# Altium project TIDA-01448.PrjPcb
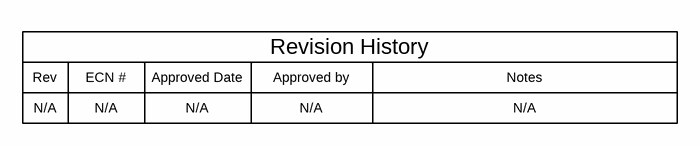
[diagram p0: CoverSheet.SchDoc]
CopyrightYear: 2015; EVM_Orderable: N/A; PCB_Layout: Who did the Layout?; PCB_Rev: E1; PRJ_Customer: Public Release; PRJ_Engineer: Enter name of project lead; PRJ_Number: TIDA-xxxxx; PRJ_Title: Change in menu Project|Project Options|Parameters; SCH_Rev: E1; TechSupport: http://www.ti.com/support; TID: ChangeMe!
3 sheets, 37 parts. Net scope: global (net labels, ports and power ports of the same name join across sheets).
Board file: TIDA-01448 Rev A1.PcbDoc
Sheets:
  CoverSheet.SchDoc
  TIDA-01448.SchDoc
  TID_Hardware.SchDoc

## Sheet CoverSheet.SchDoc
size 431 x 279 mm; Date: Not shown in title block; ApprovedBy: Not shown in title block; CheckedBy: Not shown in title block; Author: Not shown in title block; CompanyName: Not shown in title block; Engineer: Not shown in title block; Organization: Not shown in title block; Address1: Not shown in title block; Address2: Not shown in title block; Address3: Not shown in title block; Address4: Not shown in title block; DocumentNumber: 1; Revision: Use project parameter SCH_Rev; SheetNumber: 1; SheetTotal: 3; PageSetup: Record=PageOptions¦CenterHorizontal=True¦CenterVertical=True¦PrintScale=1.00¦XCorrection=1.00¦YCorrection=1.00¦PrintKind=0¦BorderSize=5000000¦LeftOffset=0¦BottomOffset=0¦Orientation=2¦PaperLength=1000¦PaperWidth=1000¦Scale=100¦PaperSource=15¦PrintQuality=600¦MediaType=1¦DitherType=10¦PaperKind=Letter¦PrintScaleMode=1

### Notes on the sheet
- Rev
- N/A
- ECN #
- Approved Date
- Approved by
- Revision History
- Notes

## Sheet TIDA-01448.SchDoc
size 431 x 279 mm; Date: Not shown in title block; ApprovedBy: Not shown in title block; CheckedBy: Not shown in title block; Author: Not shown in title block; CompanyName: Not shown in title block; Engineer: Not shown in title block; Organization: Not shown in title block; Address1: Not shown in title block; Address2: Not shown in title block; Address3: Not shown in title block; Address4: Not shown in title block; DocumentNumber: 1; Revision: Use project parameter SCH_Rev; SheetNumber: 2; SheetTotal: 3; PageSetup: Record=PageOptions¦CenterHorizontal=True¦CenterVertical=True¦PrintScale=1.00¦XCorrection=1.00¦YCorrection=1.00¦PrintKind=0¦BorderSize=5000000¦LeftOffset=0¦BottomOffset=0¦Orientation=2¦PaperLength=1000¦PaperWidth=1000¦Scale=100¦PaperSource=15¦PrintQuality=600¦MediaType=1¦DitherType=10¦PaperKind=Letter¦PrintScaleMode=1
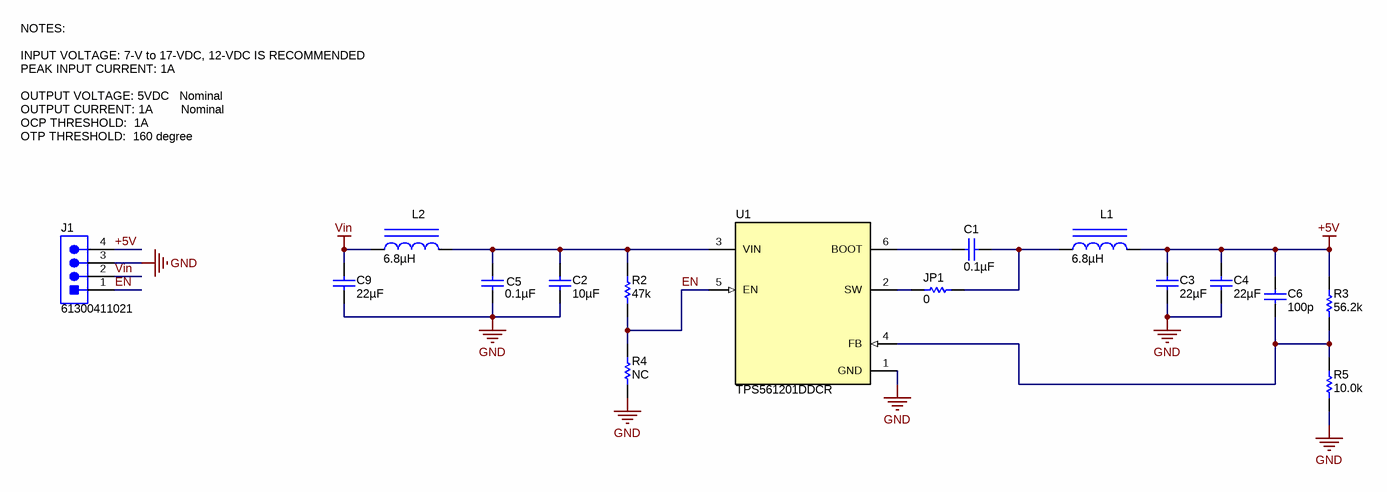
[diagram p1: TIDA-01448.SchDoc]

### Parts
C1  ValueDisplayed: 0.1µF  [0805_HV]  (hidden comment: GRM21BR71E104KA01L)
C2  ValueDisplayed: 10µF  [1206]  (hidden comment: GRM31CR71E106KA12L)
C3  ValueDisplayed: 22µF  [1206_190]  (hidden comment: GCM31CR71A226KE02)
C4  ValueDisplayed: 22µF  [1206_190]  (hidden comment: GCM31CR71A226KE02)
C5  ValueDisplayed: 0.1µF  [0603]  (hidden comment: GRM188R71E104KA01D)
C6  ValueDisplayed: 100p  [C/0805/SMT1]  (hidden comment: 06033C101KAT2A)
C9  ValueDisplayed: 22µF  [1206_190]  (hidden comment: C3216X5R1E226M160AB)
J1  61300411021  [Wurth_61300411021]
JP1  ValueDisplayed: 0  [JUMP-5]  (hidden comment: CRCW0603100KFKEA)
L1  ValueDisplayed: 6.8µH  [LPS8045B]  (hidden comment: ABG06A45M6R8)
L2  ValueDisplayed: 6.8µH  [LPS8045B]  (hidden comment: ABG03A15M6R8)
R2  ValueDisplayed: 47k  [0603]  (hidden comment: CRCW060347K0JNEA)
R3  ValueDisplayed: 56.2k  [0603]  (hidden comment: CRCW060356K2FKEA)
R4  ValueDisplayed: NC  [0603]  (hidden comment: CRCW0603150KFKEA)
R5  ValueDisplayed: 10.0k  [0603]  (hidden comment: CRCW060310K0FKEA)
U1  TPS561201DDCR  [DDC0006A_N]

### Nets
+5V: C3.1 C4.1 C6.1 J1.4 L1.2 R3.2
GND: C2.2 C3.2 C4.2 C5.2 C9.2 J1.3 R4.1 R5.1 U1.1(GND)
Vin: C9.1 J1.2 L2.1
EN: J1.1 R2.1 R4.2 U1.5(EN)
NetC1_1: C1.1 JP1.1 L1.1
NetC1_2: C1.2 U1.6(BOOT)
NetC2_1: C2.1 C5.1 L2.2 R2.2 U1.3(VIN)
NetC6_2: C6.2 R3.1 R5.2 U1.4(FB)
NetJP1_2: JP1.2 U1.2(SW)

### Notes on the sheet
- NOTES:
  INPUT VOLTAGE: 7-V to 17-VDC, 12-VDC IS RECOMMENDED
  PEAK INPUT CURRENT: 1A
  OUTPUT VOLTAGE: 5VDC   Nominal
  OUTPUT CURRENT: 1A        Nominal
  OCP THRESHOLD:  1A
  OTP THRESHOLD:  160 degree

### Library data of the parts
C1 = GRM21BR71E104KA01L: CAP, CERM, 0.1 µF, 25 V, +/- 10%, X7R, 0805; Manufacturer: MuRata; Polarized: N; CompType: Capacitor; Value: 0.1uF; U/M: EA; Cap_F: 0.0000001; Tolerance_%: 10; Value1: Unknown; VDC_V: 25; Value2: 25V; TaMin_C: -55; TaMax_C: 125; Cap_Case: 0805; AEC Category: Q200
C2 = GRM31CR71E106KA12L: CAP, CERM, 10 µF, 25 V, +/- 10%, X7R, 1206; Manufacturer: MuRata; Polarized: N; CompType: Capacitor; Value: 10uF; U/M: EA; Cap_F: 0.00001; Tolerance_%: 10; Value1: Unknown; VDC_V: 25; Value2: 25V; TaMin_C: -55; TaMax_C: 125; Cap_Case: 2220; AEC Category: Q200
C3 C4 = GCM31CR71A226KE02: CAP, CERM, 22 µF, 10 V, +/- 10%, X7R, AEC-Q200 Grade 1, 1206_190; Manufacturer: MuRata; Polarized: N; CompType: Capacitor; Value: 22uF; U/M: EA; Cap_F: 0.000022; Tolerance_%: 10; Value1: Unknown; Value2: 10V; TaMin_C: -55; TaMax_C: 125; Cap_Case: 1206; AEC Category: Q200; AEC Qualified: Y; AEC Grade: 1
C5 = GRM188R71E104KA01D: CAP, CERM, 0.1 µF, 25 V, +/- 10%, X7R, 0603; Manufacturer: MuRata; Polarized: N; CompType: Capacitor; Value: 0.1uF; U/M: EA; Cap_F: 0.0000001; Tolerance_%: 10; Value1: Unknown; VDC_V: 25; Value2: 25V; TaMin_C: -55; TaMax_C: 125; AEC Category: Q200
C6 = 06033C101KAT2A: CAP, CERM, 100 pF, 25 V, +/- 10%, X7R, 0603; Manufacturer: AVX; Polarized: N; CompType: Capacitor; Value: 100pF; U/M: EA; Cap_F: 0.0000000001; Tolerance_%: 10; Value1: Unknown; VDC_V: 25; Value2: 25V; TaMin_C: -55; TaMax_C: 125; Cap_Case: 0603; AEC Category: Q200
C9 = C3216X5R1E226M160AB: CAP, CERM, 22 µF, 25 V, +/- 20%, X5R, 1206_190; Manufacturer: TDK; Polarized: N; CompType: Capacitor; Value: 22uF; U/M: EA; Cap_F: 0.000022; Tolerance_%: 20; Value1: Unknown; VDC_V: 25; Value2: 25V; TaMin_C: -55; TaMax_C: 85; Cap_Case: 1206; AEC Category: Q200
J1 = 61300411021: Header, 2.54 mm, 4x1, Gold, R/A, TH; Manufacturer: Wurth Elektronik; SymbolCreator: a0412235; Pitch_mm: 2.54; Gender: Male; Shrouded: N; Row_Count: 1
JP1 = CRCW0603100KFKEA: RES, 100 k, 1%, 0.1 W, 0603; Manufacturer: Vishay-Dale; CompType: Resistor; Value: 100k; Res_ohm: 100000; Tolerance_%: 1; Power_W: 0.1; Value2: 0.1W; VDC_V: 75; TempCo: 100 ppm/C; EIA_Code: E96; U/M: EA; AEC Category: Q200
L1 = LPS8045B-333MRB: Inductor, Shielded, Ferrite, 3.3 µH, 6.08 A, SMD; Manufacturer: Coilcraft; Value: 6.8uH; Ind_H: 33.0E-6; Imax_A: 1.2; Irms: 1.2A @ 20C rise; Isat: 1.8A @ 10% inductance drop; DCR_ohm: 0.121; Value1: 0.121 ohm; Value2: 6.08A; AEC Category: Q200; AEC Qualified: N
L2 = LPS8045B-333MRB: Inductor, Shielded, Ferrite, 6.8 µH, 3.3 A, SMD; Manufacturer: Coilcraft; Value: 6.8uH; Ind_H: 33.0E-6; Imax_A: 1.2; Irms: 1.2A @ 20C rise; Isat: 1.8A @ 10% inductance drop; DCR_ohm: 0.121; Value1: 0.121 ohm; Value2: 0.88A; AEC Category: Q200; AEC Qualified: N
R2 = CRCW060347K0JNEA: RES, 47 k, 5%, 0.1 W, 0603; Manufacturer: Vishay-Dale; CompType: Resistor; Value: 47k; Res_ohm: 47000; Value_Code: 47k0; Tolerance_%: 5; Power_W: 0.1; Value2: 0.1W; VDC_V: 75; TempCo: 200 ppm/C; EIA_Code: E24; U/M: EA; AEC Category: Q200
R3 = CRCW060356K2FKEA: RES, 56.2 k, 1%, 0.1 W, 0603; Manufacturer: Vishay-Dale; CompType: Resistor; Value: 56.2k; Res_ohm: 56200; Value_Code: 56k2; Tolerance_%: 1; Power_W: 0.1; Value2: 0.1W; VDC_V: 75; TempCo: 100 ppm/C; EIA_Code: E96; U/M: EA; AEC Category: Q200
R4 = CRCW0603150KFKEA: RES, 150 k, 1%, 0.1 W, 0603; Manufacturer: Vishay-Dale; CompType: Resistor; Value: 150k; Res_ohm: 150000; Tolerance_%: 1; Power_W: 0.1; Value2: 0.1W; VDC_V: 75; TempCo: 100 ppm/C; EIA_Code: E96; U/M: EA; AEC Category: Q200
R5 = CRCW060310K0FKEA: RES, 10.0 k, 1%, 0.1 W, 0603; Manufacturer: Vishay-Dale; CompType: Resistor; Value: 10.0k; Res_ohm: 10000; Value_Code: 10k0; Tolerance_%: 1; Power_W: 0.1; Value2: 0.1W; VDC_V: 75; TempCo: 100 ppm/C; EIA_Code: E96; U/M: EA; AEC Category: Q200
U1 = TPS54202DDCR: 4.5-V TO 28-V INPUT, 2-A OUTPUT, EMI FRIENDLY SYNCHRONUOUS STEP-DOWN CONVERTOR, DDC0006A; Alternate PartNumber: TPS54202DDCT; Manufacturer: Texas Instruments; SymbolCreator: a0411947; CompType: IC; U/M: EA

## Sheet TID_Hardware.SchDoc
size 431 x 279 mm; Date: Not shown in title block; ApprovedBy: Not shown in title block; CheckedBy: Not shown in title block; Author: Not shown in title block; CompanyName: Not shown in title block; Engineer: Not shown in title block; Organization: Not shown in title block; Address1: Not shown in title block; Address2: Not shown in title block; Address3: Not shown in title block; Address4: Not shown in title block; DocumentNumber: 1; Revision: Use project parameter SCH_Rev; SheetNumber: 3; SheetTotal: 3; PageSetup: Record=PageOptions¦CenterHorizontal=True¦CenterVertical=True¦PrintScale=1.00¦XCorrection=1.00¦YCorrection=1.00¦PrintKind=0¦BorderSize=5000000¦LeftOffset=0¦BottomOffset=0¦Orientation=2¦PaperLength=1000¦PaperWidth=1000¦Scale=100¦PaperSource=15¦PrintQuality=600¦MediaType=1¦DitherType=10¦PaperKind=Letter¦PrintScaleMode=1
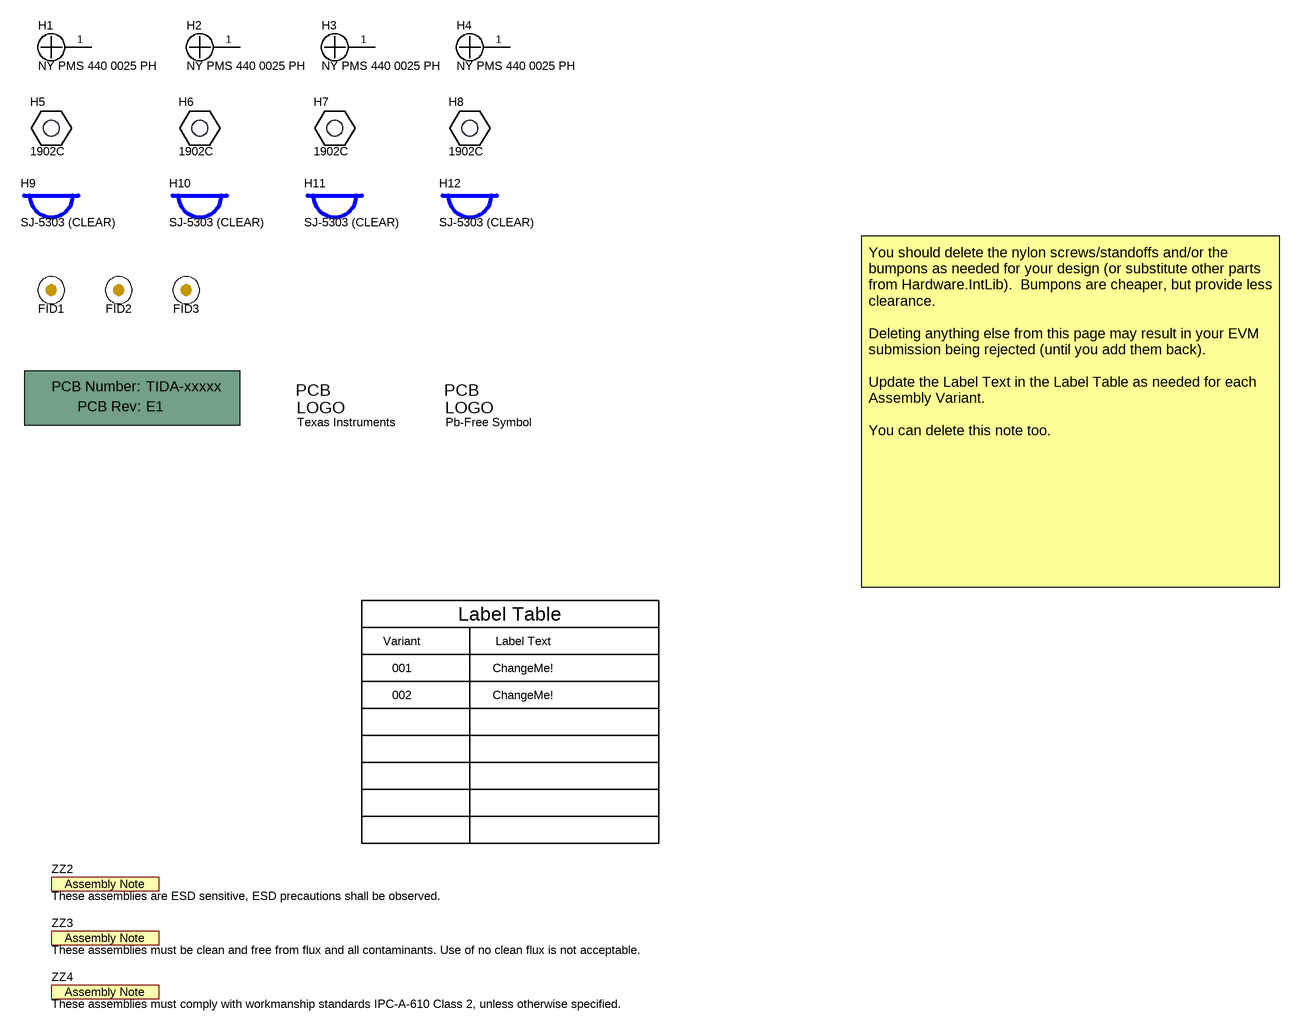
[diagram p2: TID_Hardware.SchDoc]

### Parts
!PCB  Printed Circuit Board  (value not drawn)  (mechanical)
FID1  Fiducial  [Fiducial10-20]  (value not drawn)
FID2  Fiducial  [Fiducial10-20]  (value not drawn)
FID3  Fiducial  [Fiducial10-20]  (value not drawn)
H1  NY PMS 440 0025 PH  [NY PMS 440 0025 PH]
H2  NY PMS 440 0025 PH  [NY PMS 440 0025 PH]
H3  NY PMS 440 0025 PH  [NY PMS 440 0025 PH]
H4  NY PMS 440 0025 PH  [NY PMS 440 0025 PH]
H5  1902C  [Keystone_1902C]
H6  1902C  [Keystone_1902C]
H7  1902C  [Keystone_1902C]
H8  1902C  [Keystone_1902C]
H9  SJ-5303 (CLEAR)  [Bumpon_SJ5003Transparent]
H10  SJ-5303 (CLEAR)  [Bumpon_SJ5003Transparent]
H11  SJ-5303 (CLEAR)  [Bumpon_SJ5003Transparent]
H12  SJ-5303 (CLEAR)  [Bumpon_SJ5003Transparent]
Logo1  Texas Instruments  [TI_Stacked_Overlay_Small]  (no BOM)
Logo2  Pb-Free Symbol  [Pb-Free_Overlay_Small]  (no BOM)
ZZ2  These assemblies are ESD sensitive, ESD precautions shall be observed.  [AssemblyNote]  (no BOM)
ZZ3  These assemblies must be clean and free from flux and all contaminants. Use of no clean flux is not acceptable.  [AssemblyNote]  (no BOM)
ZZ4  These assemblies must comply with workmanship standards IPC-A-610 Class 2, unless otherwise specified.  [AssemblyNote]  (no BOM)

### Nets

Not connected (* = marked no-connect by the designer): H1 1; H2 1; H3 1; H4 1

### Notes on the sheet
- Variant
- Label Table
- Label Text
- You should delete the nylon screws/standoffs and/or the bumpons as needed for your design (or substitute other parts from Hardware.IntLib).  Bumpons are cheaper, but provide less clearance.
  Deleting anything else from this page may result in your EVM submission being rejected (until you add them back).
  Update the Label Text in the Label Table as needed for each Assembly Variant.
  You can delete this note too.
- 001
- 002
- ChangeMe!

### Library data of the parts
!PCB = PCB: Manufacturer: Any; PartNumber: TIDA-xxxxx; SymbolCreator: a0412235
FID1-FID3 = Fiducial: Fiducial mark.  There is nothing to buy or mount.; SymbolCreator: codlsc
H1-H4 = NY PMS 440 0025 PH: Machine Screw, Round, #4-40 x 1/4, Nylon, Philips panhead; Manufacturer: B&F Fastener Supply; CompType: Hardware; SymbolCreator: codlsc; U/M: EA
H5-H8 = 1902C: Standoff, Hex, 0.5"L #4-40 Nylon; Manufacturer: Keystone; CompType: Hardware
H9-H12 = SJ-5303 (CLEAR): Bumpon, Hemisphere, 0.44 X 0.20, Clear; Manufacturer: 3M; SymbolCreator: a0412235
Logo1 = TI_Logo: Texas Instrument Corporate Signature; SymbolCreator: codlsc
Logo2 = Pb-Free: SymbolCreator: a0412235
ZZ2-ZZ4 = AssemblyNote: SymbolCreator: codlsc

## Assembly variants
001: not fitted FID1 FID2 FID3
